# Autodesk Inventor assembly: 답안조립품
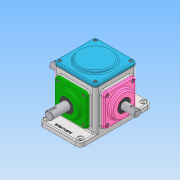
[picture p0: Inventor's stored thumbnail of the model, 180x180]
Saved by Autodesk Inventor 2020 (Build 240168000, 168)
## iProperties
Created: 2021-11
Part Number: 답안조립품
Document SubType Name: Assembly
Designer: user
Author: user
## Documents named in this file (16)
- C:\Users\user\Desktop\611112V1002\답안조립품.iam
- C:\Users\user\Desktop\611112V1002\볼트 M4.ipt
- C:\Users\user\Desktop\611112V1002\상부커버.ipt
- C:\Users\user\Desktop\611112V1002\서브베벨기어.ipt
- C:\Users\user\Desktop\611112V1002\서브축.ipt
- C:\Users\user\Desktop\611112V1002\서브커버.ipt
- C:\Users\user\Desktop\611112V1002\오일 실 17 32 8.ipt
- C:\Users\user\Desktop\611112V1002\오일 실 20 35 8.ipt
- C:\Users\user\Desktop\611112V1002\키 4x4.ipt
- C:\Users\user\Desktop\611112V1002\개스킷.ipt
- C:\Users\user\Desktop\611112V1002\메인베벨기어.ipt
- C:\Users\user\Desktop\611112V1002\메인축.ipt
- C:\Users\user\Desktop\611112V1002\메인커버.ipt
- C:\Users\user\Desktop\611112V1002\베어링 6203.ipt
- C:\Users\user\Desktop\611112V1002\베어링 6204.ipt
- C:\Users\user\Desktop\611112V1002\본체.ipt
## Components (1 placed, 1 different names)
1. 개스킷:1
